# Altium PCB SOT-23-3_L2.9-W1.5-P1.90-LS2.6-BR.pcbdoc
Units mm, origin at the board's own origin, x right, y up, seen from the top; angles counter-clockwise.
Board outline 16.45 x 15.85 mm, 2 copper layers (Top Layer, Bottom Layer), stack 0 mm thick; 1 components, 0 nets, 3 pads, 0 vias.
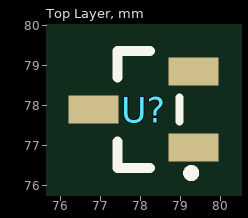
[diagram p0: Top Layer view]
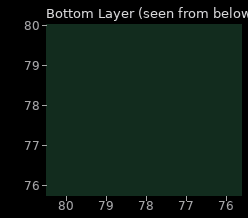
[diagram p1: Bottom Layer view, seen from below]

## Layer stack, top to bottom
Top Layer: signal copper (thickness not stored)
Bottom Layer: signal copper (thickness not stored)

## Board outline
86.299,69.85 69.85,69.85 69.85,85.698 86.299,85.698

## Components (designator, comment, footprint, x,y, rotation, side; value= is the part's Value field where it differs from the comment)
U? "" SOT-23-3_L2.9-W1.5-P1.90-LS2.6-BR 78.075,77.888 r0 top

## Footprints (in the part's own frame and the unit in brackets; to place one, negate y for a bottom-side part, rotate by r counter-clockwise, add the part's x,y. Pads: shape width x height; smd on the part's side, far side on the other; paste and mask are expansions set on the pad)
SOT-23-3_L2.9-W1.5-P1.90-LS2.6-BR [mm]
  rect 1.25x0.7 smd: 1(1.25,-0.95) 2(1.25,0.95) 3(-1.25,0)
  silkscreen extent -0.65,-1.69 1.29,1.46

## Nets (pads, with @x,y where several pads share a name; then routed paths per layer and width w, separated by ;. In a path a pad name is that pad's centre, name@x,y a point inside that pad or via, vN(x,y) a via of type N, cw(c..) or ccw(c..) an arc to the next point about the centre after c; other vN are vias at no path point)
pads on no net: U?.1 U?.2 U?.3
